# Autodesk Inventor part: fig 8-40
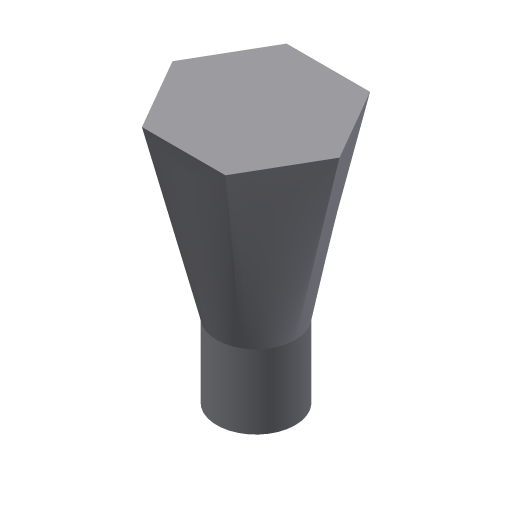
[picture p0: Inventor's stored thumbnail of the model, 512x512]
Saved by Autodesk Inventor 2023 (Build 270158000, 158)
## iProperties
Created: 2004-05
Part Number: fig 8-40
Document SubType Name: Modeling
Designer: CADCIM Technologies
Manufacturer: Standard
Standards Organization: Custom
Density: 1 g/cm^3
Material: Generic
Appearance: Default
Author: CADCIM Technologies
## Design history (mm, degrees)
sketch "Sketch1"
  geometry: C1 r 16.344 at (0, 0)
  constraints: 1 centre point
extrude "Extrusion1" new body sketch "Sketch1" distance "d0" = 30.75; taper "d1" = 0 deg
workplane "Work Plane1"
sketch "Sketch2"
  geometry: L1 (34.788, 0)-(17.394, -30.128); L2 (17.394, -30.128)-(-17.394, -30.128); L3 (-17.394, -30.128)-(-34.788, 0); L4 (-34.788, 0)-(-17.394, 30.128); L5 (-17.394, 30.128)-(17.394, 30.128); L6 (17.394, 30.128)-(34.788, 0); 2 further points
  constraints: 12 end point, 1 coincident, 12 other
loft "Loft2" sketch "Sketch2" dims "d7" = 0, "d8" = 90 deg, "d9" = 0, "d10" = 90 deg
  node "Edges2"
body "Solid1"
other parameters: "d2" = 75
